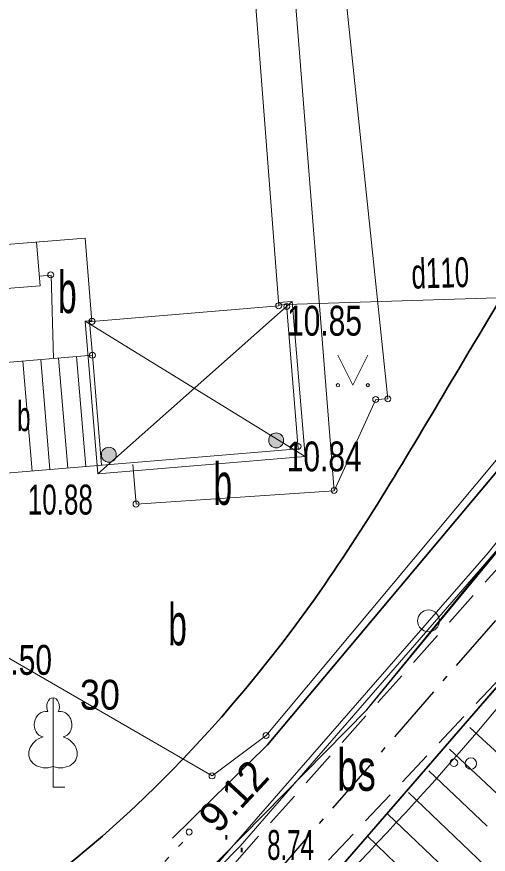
# Model space of a CAD drawing. Extents: x 514052 to 514314, y 297701 to 297876.
# Drawn here: x 514240.99 to 514248.88, y 297791.45 to 297805.47 of the extents above; entities that cross this region are included whole.
import ezdxf
from ezdxf.enums import TextEntityAlignment as Align

# ---------------------------------------------------------------- set-up
doc = ezdxf.new("R2010")
doc.units = 0
doc.header["$LTSCALE"] = 0.2
for name, pattern in [('DOT_DASHED', [7.7, 5, -1.2, 0.3, -1.2]), ('DOTTED', [1.5, 0.3, -1.2]), ('MEDIUM_DASHED', [4.5, 3, -1.5])]:
    doc.linetypes.add(name, pattern=pattern)
for name, color, linetype, lineweight in [('1', 7, 'Continuous', 13), ('11', 7, 'Continuous', 35), ('19', 7, 'Continuous', 25), ('3', 7, 'Continuous', 13), ('35', 7, 'Continuous', 25), ('5', 7, 'Continuous', 13), ('55', 7, 'Continuous', 13), ('56', 7, 'Continuous', 13), ('57', 7, 'DOTTED', 13), ('59', 7, 'Continuous', 13), ('6', 7, 'Continuous', 13), ('60', 7, 'Continuous', 13), ('61', 7, 'Continuous', 13), ('62', 7, 'Continuous', 13), ('63', 7, 'Continuous', 13), ('7', 7, 'Continuous', 13)]:
    doc.layers.add(name, color=color, linetype=linetype, lineweight=lineweight)
for name, color, linetype in [('10', 7, 'Continuous'), ('12', 7, 'Continuous'), ('15', 7, 'Continuous'), ('8', 7, 'Continuous')]:
    doc.layers.add(name, color=color, linetype=linetype)

msp = doc.modelspace()

# ---------------------------------------------------------------- hatches: boundary and pattern name
at = {"layer": '7'}
for points in [[(514245.452, 297798.3791, 1), (514245.202, 297798.3791, 1)], [(514242.6519, 297798.1381, 1), (514242.4019, 297798.1381, 1)]]:
    msp.add_hatch(color=256, dxfattribs=at).paths.add_polyline_path(points)

# ---------------------------------------------------------------- linework, layer by layer
at = {"layer": '1'}
for p, q in [((514248.57, 297793.575), (514249.554, 297792.656)), ((514248.228, 297793.211), (514251.49, 297790.135)), ((514247.884, 297792.847), (514248.86, 297791.923)), ((514247.54, 297792.484), (514250.781, 297789.394)), ((514247.195, 297792.123), (514248.166, 297791.194)), ((514246.849, 297791.762), (514250.084, 297788.657))]:
    msp.add_line(p, q, dxfattribs=at)
msp.add_circle((514247.8773, 297795.3573), 0.1827, dxfattribs=at)
msp.add_spline([(514260.862, 297805.466), (514258.749, 297804.839), (514257.459, 297803.011), (514254.953, 297800.933), (514250.105, 297795.245), (514240.136, 297784.718), (514236.07, 297778.812), (514235.246, 297774.955), (514233.92, 297771.109), (514234.456, 297764.804)], degree=3, dxfattribs=at)
at = {"layer": '11'}
msp.add_lwpolyline([(514243.591, 297791.72), (514245.183, 297793.281), (514249.573, 297798.519), (514251.063, 297800.706)], dxfattribs=at)
at = {"layer": '19', "lineweight": 13}
msp.add_spline([(514243.205, 297765.058), (514242.936, 297773.769), (514245.025, 297781.038), (514246.54, 297783.925), (514249.054, 297787.013), (514257.225, 297795.21), (514260.154, 297798.886), (514267.863, 297801.516), (514273.305, 297805.826), (514276.583, 297807.615)], degree=3, dxfattribs=at)
at = {"layer": '3'}
msp.add_line((514245.502, 297800.655), (514254.884, 297800.949), dxfattribs=at)
at = {"layer": '35'}
msp.add_lwpolyline([(514231.97, 297771.331), (514233.541, 297774.128), (514233.667, 297780.485), (514240.255, 297787.177), (514246.843, 297793.868), (514250.774, 297798.68), (514254.387, 297803.352), (514256.058, 297805.511), (514258.694, 297808.915), (514260.151, 297809.248), (514268.632, 297811.186)], dxfattribs=at)
at = {"layer": '35', "lineweight": 35}
msp.add_lwpolyline([(514271.3, 297810.152), (514259.606, 297807.499), (514252.681, 297798.474), (514245.829, 297790.57), (514238.515, 297783.139), (514236.323, 297779.764), (514235.19, 297775.821), (514235.133, 297773.758), (514233.372, 297770.559)], dxfattribs=at)
at = {"layer": '5'}
for p, q in [((514241.593, 297794.072), (514241.593, 297792.919)), ((514241.683, 297793.84), (514241.682, 297793.841)), ((514241.593, 297792.919), (514241.593, 297792.572)), ((514241.593, 297792.572), (514241.793, 297792.572))]:
    msp.add_line(p, q, dxfattribs=at)
msp.add_lwpolyline([(514246.361, 297799.803), (514246.611, 297799.303), (514246.861, 297799.803)], dxfattribs=at)
for centre, radius in [((514246.3604, 297799.3027), 0.028), ((514246.8604, 297799.3027), 0.0263), ((514248.3016, 297792.9824), 0.064), ((514248.586, 297792.9689), 0.096)]:
    msp.add_circle(centre, radius, dxfattribs=at)
for centre, major_axis, ratio, start_param, end_param in [((514241.5934, 297793.9222), (0, -0.1499), 0.707107, 3.1453698, 5.2874846), ((514241.5925, 297793.9222), (0, -0.1499), 0.707107, 0.9957007, 3.1378155), ((514241.4647, 297793.6274), (-0.0387, -0.2124), 0.861323, 3.1415927, 6.2831853), ((514241.7212, 297793.6274), (0.0387, -0.2124), 0.861323, 6.2831853, 9.424778), ((514241.5034, 297793.1651), (0.3068, 0.0951), 0.814445, 1.5707963, 4.7520146), ((514241.6825, 297793.1651), (-0.3068, 0.0951), 0.814445, 1.5311707, 4.712389)]:
    msp.add_ellipse(centre, major_axis=major_axis, ratio=ratio, start_param=start_param, end_param=end_param, dxfattribs=at)
at = {"layer": '55'}
msp.add_lwpolyline([(514217.339, 297769.84), (514231.97, 297771.331), (514233.541, 297774.128), (514233.602, 297778.964), (514248.877, 297796.499), (514258.817, 297808.985), (514270.863, 297811.577), (514272.894, 297813.849)], dxfattribs=at)
at = {"layer": '56'}
for p, q in [((514241.315, 297801.699), (514241.375, 297800.964)), ((514239.672, 297800.832), (514241.375, 297800.964)), ((514245.368, 297800.645), (514245.502, 297800.655)), ((514245.502, 297800.655), (514245.697, 297798.237)), ((514242.244, 297800.371), (514242.204, 297800.368)), ((514242.204, 297800.368), (514242.251, 297799.804)), ((514239.893, 297799.607), (514242.251, 297799.804)), ((514241.986, 297799.782), (514242.14, 297797.94)), ((514242.251, 297799.804), (514242.405, 297797.962)), ((514241.089, 297799.707), (514241.243, 297797.865)), ((514241.388, 297799.732), (514241.542, 297797.89)), ((514241.687, 297799.757), (514241.841, 297797.915)), ((514240.047, 297797.765), (514245.697, 297798.237))]:
    msp.add_line(p, q, dxfattribs=at)
at = {"layer": '57', "lineweight": 25}
msp.add_line((514243.763, 297791.654), (514232.997, 297780.053), dxfattribs=at)
at = {"layer": '59'}
for p, q in [((514244.841, 297807.586), (514245.369, 297800.632)), ((514242.13, 297801.766), (514238.817, 297801.496)), ((514242.13, 297801.766), (514242.244, 297800.371)), ((514242.244, 297800.371), (514245.369, 297800.632))]:
    msp.add_line(p, q, dxfattribs=at)
at = {"layer": '6'}
for centre in [(514241.5539, 297801.1491), (514245.3689, 297800.6321), (514245.5049, 297800.6211), (514242.2439, 297800.3711), (514242.251, 297799.8041), (514246.9929, 297799.0641), (514247.196, 297799.0742), (514245.6939, 297798.2771), (514246.2969, 297797.5412), (514242.9819, 297797.3132), (514245.158, 297793.4391), (514244.2539, 297792.7631), (514243.8708, 297791.8229)]:
    msp.add_circle(centre, 0.05, dxfattribs=at)
at = {"layer": '60'}
for p, q in [((514242.344, 297797.817), (514245.597, 297800.706)), ((514245.365, 297800.688), (514245.597, 297800.706)), ((514245.597, 297800.706), (514245.814, 297798.107)), ((514242.243, 297800.386), (514242.13, 297800.377)), ((514242.13, 297800.377), (514242.344, 297797.817)), ((514242.13, 297800.377), (514245.814, 297798.107)), ((514242.344, 297797.817), (514245.814, 297798.107))]:
    msp.add_line(p, q, dxfattribs=at)
at = {"layer": '61'}
for points in [[(514246.843, 297793.868), (514250.081, 297797.789), (514258.694, 297808.915), (514270.983, 297811.723)], [(514219.342, 297770.059), (514231.967, 297771.335), (514233.539, 297774.175), (514233.667, 297780.485), (514246.843, 297793.868)]]:
    msp.add_lwpolyline(points, dxfattribs=at)
at = {"layer": '62'}
msp.add_spline([(514242.228, 297765.875), (514240.809, 297773.912), (514243.289, 297779.448), (514244.466, 297781.572), (514244.559, 297781.63), (514245.987, 297783.723), (514248.871, 297787.176), (514251.243, 297789.878), (514252.476, 297791.159), (514253.723, 297792.429), (514256.513, 297795.415), (514260.533, 297799.834), (514263.587, 297801.907), (514261.268, 297805.481)], degree=3, dxfattribs=at)
at = {"layer": '63'}
for p, q in [((514245.467, 297807.986), (514246.3, 297797.534)), ((514241.562, 297801.145), (514241.362, 297801.129)), ((514241.6, 297799.75), (514241.562, 297801.145)), ((514246.3, 297797.534), (514246.993, 297799.064)), ((514242.982, 297797.313), (514242.927, 297797.973)), ((514242.982, 297797.313), (514246.3, 297797.534))]:
    msp.add_line(p, q, dxfattribs=at)
for points in [[(514240.25, 297797.788), (514240.461, 297794.955), (514244.254, 297792.763), (514245.158, 297793.439), (514249.384, 297798.494), (514249.574, 297803.112), (514249.804, 297806.229), (514250.567, 297808.046), (514251.305, 297808.79), (514254.642, 297812.211), (514253.566, 297813.059)], [(514241.033, 297787.835), (514244.727, 297791.588), (514248.123, 297795.505), (514251.519, 297799.422), (514255.132, 297804.131), (514258.746, 297808.841), (514264.857, 297810.227), (514270.968, 297811.614), (514271.3, 297810.152), (514259.609, 297807.499), (514256.144, 297802.987), (514253.336, 297799.341), (514249.255, 297794.522), (514245.829, 297790.57)], [(514246.248, 297791.053), (514247.856, 297792.907), (514251.587, 297797.176), (514252.569, 297798.349), (514254.104, 297800.332), (514255.107, 297801.628), (514257.105, 297804.234), (514259.609, 297807.499), (514265.761, 297808.894), (514271.304, 297810.15), (514273.327, 297806.65), (514267.17, 297803.809), (514264.799, 297803.032), (514260.928, 297799.431), (514257.141, 297794.684), (514253.744, 297790.866)], [(514246.993, 297799.064), (514247.196, 297799.074), (514246.215, 297808.465)]]:
    msp.add_lwpolyline(points, dxfattribs=at)
at = {"layer": '63', "linetype": 'MEDIUM_DASHED'}
for points in [[(514231.583, 297765.652), (514232.855, 297769.107), (514235.126, 297775.062), (514235.802, 297779.27), (514240.035, 297784.801), (514250.098, 297795.488), (514254.893, 297801.043), (514257.448, 297803.118), (514259.485, 297807.223), (514261.814, 297808.455), (514265.145, 297808.86), (514272.105, 297811.112)], [(514249.225, 297796.455), (514239.453, 297785.495), (514234.344, 297779.635), (514234.008, 297775.04), (514233.159, 297771.888), (514231.647, 297770.296), (514228.019, 297768.169)]]:
    msp.add_lwpolyline(points, dxfattribs=at)
at = {"layer": '63', "linetype": 'DOT_DASHED', "lineweight": 25}
msp.add_lwpolyline([(514271.134, 297810.883), (514259.176, 297808.17), (514252.1, 297798.948), (514245.278, 297791.079), (514237.927, 297783.611), (514235.633, 297780.079), (514234.443, 297775.937), (514234.388, 297773.96), (514232.332, 297770.225), (514229.92, 297766.887)], dxfattribs=at)
at = {"layer": '63', "lineweight": 35}
msp.add_spline([(514235.586, 297788.069), (514238.834, 297789.344), (514246.139, 297795.966), (514248.394, 297799.596), (514253.835, 297808.327)], degree=3, dxfattribs=at)
at = {"layer": '7'}
for centre in [(514245.327, 297798.3791), (514242.5269, 297798.1381)]:
    msp.add_circle(centre, 0.125, dxfattribs=at)

# ---------------------------------------------------------------- texts
at = {"layer": '10'}
for s, width, p in [('b', 0.6, (514241.8325, 297800.511)), ('b', 0.6, (514244.4345, 297797.3)), ('b', 0.6, (514243.6775, 297794.949)), ('bs', 0.65, (514246.672, 297792.514))]:
    msp.add_text(s, height=0.7, dxfattribs=dict(at, width=width)).set_placement(p, align=Align.CENTER)
at = {"layer": '11', "width": 0.65}
msp.add_text('d110', height=0.5, rotation=1.795, dxfattribs=at).set_placement((514248.0812, 297800.933), align=Align.CENTER)
at = {"layer": '12', "width": 0.9}
msp.add_text('30      ', height=0.5, dxfattribs=at).set_placement((514242.043, 297793.872))
at = {"layer": '15', "width": 0.6}
msp.add_text('b', height=0.5, dxfattribs=at).set_placement((514240.993, 297798.534))
at = {"layer": '8'}
for s, width, p in [(' 10.85', 0.75, (514245.369, 297800.132)), (' 10.84', 0.75, (514245.364, 297797.86)), ('10.88', 0.65, (514241.171, 297797.138)), (' 9.50', 0.75, (514240.461, 297794.455)), ('.', 0.5, (514244.448, 297791.696)), ('8.74', 0.6, (514245.177, 297791.358)), ('.', 0.5, (514244.705, 297791.482))]:
    msp.add_text(s, height=0.5, dxfattribs=dict(at, width=width)).set_placement(p)
msp.add_text(' 9.12', height=0.5, rotation=47.084, dxfattribs=at).set_placement((514244.226, 297791.642))

doc.saveas('drawing.dxf')
